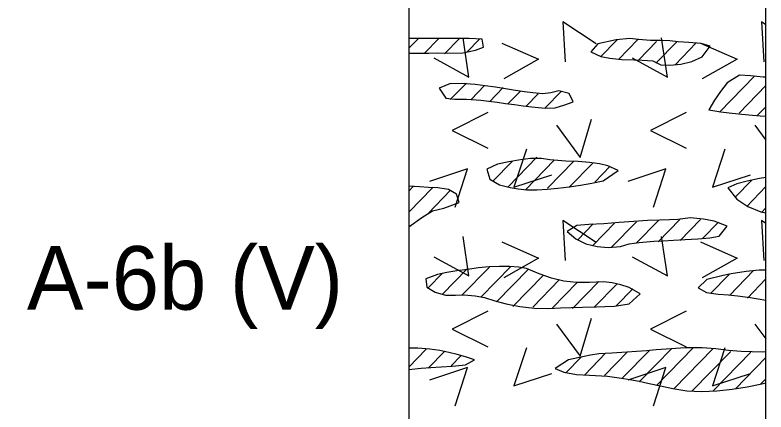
# Model space of a CAD drawing. Extents: x 0 to 0.83, y -0.65 to 1.27.
# Drawn here: x 0.7545 to 0.8333, y 0.9546 to 0.9962 of the extents above; entities that cross this region are included whole.
import ezdxf

# ---------------------------------------------------------------- set-up
doc = ezdxf.new("R2010")
doc.units = 0

msp = doc.modelspace()

# ---------------------------------------------------------------- linework, layer by layer
for points in [[(0, 0), (0.833332, 0), (0.833332, 1.274997), (0, 1.274997)], [(0, 0), (0.833332, 0), (0.833332, 1.274997), (0, 1.274997)], [(0, 0), (0.833332, 0), (0.833332, 1.274997), (0, 1.274997)], [(0, 0), (0.833332, 0), (0.833332, 1.274997), (0, 1.274997)], [(0, 0), (0.833332, 0), (0.833332, 1.274997), (0, 1.274997)], [(0.795832, 0.992177), (0.796757, 0.992167), (0.797925, 0.992186), (0.798816, 0.992225), (0.799915, 0.992182), (0.801515, 0.992226), (0.802823, 0.992483), (0.803666, 0.992802), (0.80354, 0.993641), (0.802165, 0.993726), (0.795832, 0.993726)], [(0.818216, 0.991532), (0.819444, 0.991473), (0.820325, 0.991433), (0.821453, 0.991365), (0.822286, 0.990951), (0.82324, 0.990907), (0.824378, 0.991012), (0.825554, 0.991301), (0.826624, 0.991805), (0.82749, 0.992902), (0.826513, 0.993205), (0.825239, 0.993306), (0.82413, 0.99337), (0.823236, 0.993476), (0.822257, 0.993495), (0.821211, 0.993519), (0.819948, 0.993611), (0.819024, 0.993726), (0.817611, 0.993587), (0.815663, 0.993143), (0.814958, 0.992304), (0.815983, 0.991816), (0.816947, 0.99164)], [(0.833053, 0.989678), (0.831709, 0.98979), (0.830539, 0.989891), (0.829246, 0.989071), (0.828567, 0.988157), (0.827924, 0.98727), (0.827345, 0.986244), (0.828579, 0.986018), (0.829451, 0.985917), (0.830451, 0.98582), (0.831549, 0.985725), (0.832716, 0.985628), (0.833332, 0.985577), (0.833332, 0.989669)], [(0.800664, 0.987375), (0.801881, 0.987368), (0.803392, 0.98724), (0.804229, 0.987144), (0.805103, 0.987034), (0.806004, 0.986916), (0.806919, 0.986795), (0.807838, 0.986677), (0.808747, 0.986567), (0.810142, 0.986425), (0.811186, 0.986437), (0.812223, 0.986782), (0.81308, 0.987067), (0.812673, 0.987969), (0.811597, 0.988216), (0.810749, 0.988018), (0.809892, 0.987935), (0.808847, 0.988016), (0.807995, 0.988127), (0.807033, 0.988271), (0.805997, 0.988435), (0.804922, 0.988602), (0.803843, 0.988759), (0.802797, 0.988891), (0.801817, 0.988983), (0.800202, 0.988992), (0.799007, 0.988519), (0.79974, 0.987477)], [(0.812326, 0.98087), (0.810635, 0.980988), (0.809773, 0.981122), (0.808601, 0.981129), (0.807553, 0.980985), (0.806321, 0.980786), (0.805133, 0.980543), (0.804031, 0.980022), (0.804359, 0.978961), (0.805363, 0.978394), (0.806466, 0.978096), (0.807303, 0.977945), (0.80824, 0.977869), (0.80926, 0.97786), (0.810349, 0.977911), (0.811489, 0.978013), (0.812666, 0.97816), (0.813863, 0.978344), (0.815063, 0.978557), (0.816252, 0.978791), (0.81783, 0.979872), (0.816735, 0.980371), (0.815852, 0.980573), (0.814797, 0.980731), (0.813609, 0.980833)], [(0.832654, 0.979057), (0.831362, 0.978748), (0.830275, 0.978473), (0.829339, 0.978079), (0.830265, 0.976879), (0.831418, 0.976116), (0.832792, 0.975538), (0.833332, 0.975439), (0.833332, 0.979148)], [(0.795832, 0.973961), (0.79719, 0.974951), (0.798312, 0.975653), (0.799509, 0.975924), (0.801112, 0.976525), (0.800861, 0.977409), (0.800021, 0.977885), (0.798893, 0.978079), (0.797908, 0.978109), (0.796943, 0.978166), (0.795832, 0.978249)], [(0.825375, 0.974904), (0.824078, 0.974754), (0.823187, 0.974697), (0.822142, 0.974673), (0.820907, 0.974636), (0.819474, 0.974544), (0.817918, 0.974423), (0.816318, 0.974303), (0.814751, 0.974211), (0.813476, 0.97411), (0.812472, 0.973471), (0.813366, 0.97271), (0.814436, 0.972205), (0.815612, 0.971917), (0.816749, 0.971812), (0.818067, 0.971924), (0.818959, 0.9722), (0.820031, 0.972344), (0.821573, 0.972466), (0.82253, 0.972524), (0.823615, 0.972582), (0.824832, 0.972644), (0.826183, 0.97271), (0.827451, 0.972818), (0.828416, 0.972993), (0.829268, 0.974048), (0.827909, 0.974565), (0.826788, 0.974764)], [(0.798854, 0.968995), (0.797634, 0.968534), (0.797728, 0.967639), (0.798587, 0.967115), (0.799696, 0.966819), (0.800742, 0.966829), (0.801652, 0.966843), (0.802809, 0.96676), (0.803766, 0.966552), (0.804856, 0.966203), (0.80606, 0.965906), (0.807509, 0.965632), (0.809046, 0.965446), (0.810517, 0.965416), (0.811769, 0.965473), (0.812889, 0.965514), (0.814075, 0.965549), (0.815527, 0.965589), (0.816416, 0.965615), (0.817445, 0.965647), (0.818967, 0.96592), (0.820111, 0.966956), (0.818963, 0.967625), (0.818099, 0.967892), (0.817169, 0.968089), (0.816265, 0.968194), (0.814793, 0.968135), (0.813435, 0.968138), (0.812104, 0.968288), (0.810802, 0.96859), (0.809527, 0.969051), (0.808198, 0.9696), (0.807356, 0.96976), (0.806403, 0.969834), (0.805364, 0.969835), (0.804267, 0.969775), (0.803138, 0.969666), (0.802006, 0.969521), (0.800896, 0.969353), (0.799837, 0.969173)], [(0.832629, 0.969442), (0.831261, 0.969304), (0.829688, 0.969039), (0.828826, 0.968865), (0.82712, 0.968455), (0.826226, 0.967586), (0.827084, 0.967094), (0.828308, 0.966907), (0.829408, 0.966842), (0.830335, 0.966753), (0.831655, 0.96657), (0.832526, 0.966428), (0.833332, 0.966286), (0.833332, 0.969434)], [(0.795832, 0.959038), (0.797147, 0.959149), (0.798141, 0.959222), (0.799224, 0.959299), (0.800394, 0.959384), (0.80179, 0.959506), (0.802748, 0.960021), (0.801793, 0.960363), (0.800911, 0.960577), (0.800027, 0.960797), (0.79909, 0.961004), (0.798029, 0.961169), (0.79677, 0.961265), (0.795832, 0.961244)], [(0.828162, 0.956791), (0.82978, 0.95696), (0.831374, 0.957212), (0.832902, 0.957523), (0.833332, 0.957628), (0.833332, 0.960868), (0.832951, 0.960835), (0.831885, 0.960857), (0.830714, 0.96091), (0.829383, 0.961012), (0.828069, 0.961181), (0.826619, 0.961301), (0.825765, 0.961303), (0.824843, 0.961276), (0.823868, 0.961225), (0.822856, 0.961157), (0.82182, 0.961077), (0.820774, 0.960993), (0.819735, 0.96091), (0.818715, 0.960835), (0.817148, 0.96074), (0.815785, 0.960647), (0.814914, 0.960514), (0.813574, 0.96024), (0.812595, 0.960027), (0.811206, 0.959109), (0.812105, 0.958746), (0.813452, 0.958501), (0.814789, 0.95841), (0.816678, 0.958307), (0.818181, 0.958107), (0.819046, 0.957961), (0.820004, 0.957782), (0.821067, 0.957568), (0.82225, 0.957316), (0.823565, 0.957024), (0.825013, 0.956799), (0.826559, 0.956729)]]:
    msp.add_lwpolyline(points, close=True)
for points in [[(0.795832, 1.220831), (0.795832, -0.645749)], [(0.833332, -0.645749), (0.833332, 1.133648)], [(0.815512, 0.993158), (0.812012, 0.995471), (0.812262, 0.991283)], [(0.833332, 0.995149), (0.832845, 0.995471), (0.833095, 0.991283)], [(0.795832, 0.992696), (0.796808, 0.993696)], [(0.798985, 0.993714), (0.797473, 0.992165)], [(0.798466, 0.991676), (0.802154, 0.989676), (0.801529, 0.993801)], [(0.801161, 0.993731), (0.799593, 0.992124)], [(0.803281, 0.993691), (0.801883, 0.992259)], [(0.817701, 0.99359), (0.815961, 0.991807)], [(0.819878, 0.993607), (0.817852, 0.991531)], [(0.8193, 0.991676), (0.822987, 0.989676), (0.822362, 0.993801)], [(0.821854, 0.993419), (0.819972, 0.99149)], [(0.824002, 0.993407), (0.821778, 0.991128)], [(0.805617, 0.993221), (0.809456, 0.991537), (0.805806, 0.989476)], [(0.826007, 0.99325), (0.823783, 0.99097)], [(0.82645, 0.993221), (0.83029, 0.991537), (0.826639, 0.989476)], [(0.832167, 0.989804), (0.828441, 0.985987)], [(0.801877, 0.98903), (0.800195, 0.987307)], [(0.803798, 0.988786), (0.80237, 0.987324)], [(0.805745, 0.988569), (0.804291, 0.987079)], [(0.833332, 0.988785), (0.830521, 0.985905)], [(0.80758, 0.988236), (0.806268, 0.986891)], [(0.809414, 0.987903), (0.808159, 0.986617)], [(0.811876, 0.988213), (0.810165, 0.986459)], [(0.833332, 0.986572), (0.832451, 0.985669)], [(0.804125, 0.985963), (0.800375, 0.984088), (0.804125, 0.982213)], [(0.824958, 0.985963), (0.821208, 0.984088), (0.824958, 0.982213)], [(0.811342, 0.984622), (0.813842, 0.981247), (0.815029, 0.985247)], [(0.832175, 0.984622), (0.833332, 0.98306)], [(0.808181, 0.982131), (0.806868, 0.978131), (0.810868, 0.979444)], [(0.829014, 0.982131), (0.827702, 0.978131), (0.831702, 0.979444)], [(0.804649, 0.978753), (0.806674, 0.980828)], [(0.806256, 0.978186), (0.809278, 0.981283)], [(0.80809, 0.977853), (0.811113, 0.98095)], [(0.810409, 0.978017), (0.813175, 0.980851)], [(0.812643, 0.978093), (0.815181, 0.980693)], [(0.800689, 0.976051), (0.802002, 0.980051), (0.798002, 0.978738)], [(0.815361, 0.978665), (0.816987, 0.980331)], [(0.821523, 0.976051), (0.822835, 0.980051), (0.818835, 0.978738)], [(0.830098, 0.977091), (0.831838, 0.978874)], [(0.796303, 0.978207), (0.795832, 0.977723)], [(0.798338, 0.978079), (0.795832, 0.975511)], [(0.797862, 0.975379), (0.800229, 0.977804)], [(0.831305, 0.976116), (0.833332, 0.978192)], [(0.832854, 0.97549), (0.833332, 0.975979)], [(0.815512, 0.972325), (0.812012, 0.974637), (0.812262, 0.97045)], [(0.815145, 0.972013), (0.817482, 0.974408)], [(0.817092, 0.971796), (0.819744, 0.974512)], [(0.819696, 0.972251), (0.822034, 0.974648)], [(0.822015, 0.972414), (0.824297, 0.974752)], [(0.824306, 0.972549), (0.826445, 0.974741)], [(0.826625, 0.972713), (0.828336, 0.974466)], [(0.833332, 0.974316), (0.832845, 0.974637), (0.833095, 0.97045)], [(0.815192, 0.974275), (0.813538, 0.972579)], [(0.798466, 0.970842), (0.802154, 0.968842), (0.801529, 0.972967)], [(0.8193, 0.970842), (0.822987, 0.968842), (0.822362, 0.972967)], [(0.805617, 0.972388), (0.809456, 0.970704), (0.805806, 0.968642)], [(0.82645, 0.972388), (0.83029, 0.970704), (0.826639, 0.968642)], [(0.801419, 0.966799), (0.804299, 0.96975)], [(0.806532, 0.969826), (0.803395, 0.966611)], [(0.799375, 0.969131), (0.797863, 0.967581)], [(0.799328, 0.966869), (0.801951, 0.969557)], [(0.805059, 0.966103), (0.808397, 0.969524)], [(0.809973, 0.968926), (0.806747, 0.96562)], [(0.827512, 0.966978), (0.82945, 0.968963)], [(0.832025, 0.96939), (0.829489, 0.966791)], [(0.811636, 0.968418), (0.808841, 0.965554)], [(0.813527, 0.968142), (0.810936, 0.965488)], [(0.813032, 0.965422), (0.815789, 0.968248)], [(0.831379, 0.966515), (0.833332, 0.968516)], [(0.815342, 0.965577), (0.817681, 0.967973)], [(0.817605, 0.965682), (0.819344, 0.967465)], [(0.833327, 0.966299), (0.833332, 0.966304)], [(0.804125, 0.96513), (0.800375, 0.963255), (0.804125, 0.96138)], [(0.824958, 0.96513), (0.821208, 0.963255), (0.824958, 0.96138)], [(0.811342, 0.963789), (0.813842, 0.960414), (0.815029, 0.964414)], [(0.832175, 0.963789), (0.833332, 0.962227)], [(0.797655, 0.961152), (0.795832, 0.959283)], [(0.808181, 0.961298), (0.806868, 0.957298), (0.810868, 0.95861)], [(0.818285, 0.958131), (0.821137, 0.961053)], [(0.820035, 0.957711), (0.823455, 0.961216)], [(0.825691, 0.961293), (0.82184, 0.957348)], [(0.827752, 0.961193), (0.823702, 0.957044)], [(0.829014, 0.961298), (0.827702, 0.957298), (0.831702, 0.95861)], [(0.799604, 0.960936), (0.797864, 0.959154)], [(0.801295, 0.960457), (0.800268, 0.959405)], [(0.813923, 0.960299), (0.812354, 0.958692)], [(0.814303, 0.958476), (0.816499, 0.960725)], [(0.816395, 0.958407), (0.818789, 0.960861)], [(0.829644, 0.960918), (0.825565, 0.95674)], [(0.831735, 0.960849), (0.827743, 0.956759)], [(0.833332, 0.960272), (0.830118, 0.956979)], [(0.800689, 0.955218), (0.802002, 0.959218), (0.798002, 0.957905)], [(0.821523, 0.955218), (0.822835, 0.959218), (0.818835, 0.957905)], [(0.832808, 0.957523), (0.833332, 0.958059)]]:
    msp.add_lwpolyline(points)

# ---------------------------------------------------------------- texts
msp.add_text('A-6b (V)', height=0.0066667).set_placement((0.755748, 0.96529))

doc.saveas('drawing.dxf')
